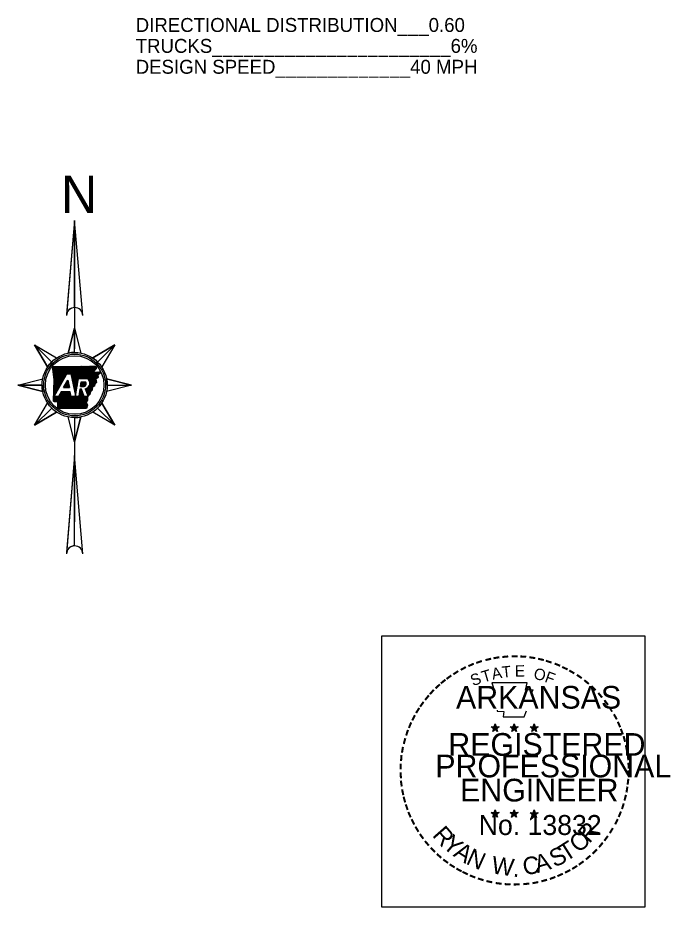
# Model space of a CAD drawing. Extents: x 541267 to 698737, y 790528 to 880942.
# Drawn here: x 633670 to 661200, y 793053 to 830549 of the extents above; entities that cross this region are included whole.
import ezdxf

# ---------------------------------------------------------------- set-up
doc = ezdxf.new("R2010")
doc.units = 0
for name, color, linetype in [('R_Border PE_RWC', 7, 'Continuous'), ('R_Draft', 7, 'Continuous'), ('R_No Plot', 7, 'Continuous'), ('R_Water Annot', 7, 'Continuous')]:
    doc.layers.add(name, color=color, linetype=linetype)

msp = doc.modelspace()

# ---------------------------------------------------------------- linework, layer by layer
at = {"layer": 'R_Border PE_RWC'}
for p, q in [((653647, 800662), (653814, 800609)), ((653647, 800662), (653768, 800640)), ((653647, 800662), (653761, 800603)), ((653711, 800467), (653814, 800609)), ((653711, 800467), (653771, 800583)), ((653711, 800467), (653813, 800570)), ((653814, 800783), (653795, 800663)), ((653916, 800467), (653813, 800569)), ((653814, 800609), (653814, 800783)), ((653814, 800783), (653838, 800664)), ((653980, 800662), (653814, 800609)), ((653916, 800467), (653814, 800609)), ((653980, 800662), (653843, 800638)), ((653916, 800467), (653851, 800606)), ((653980, 800662), (653883, 800613)), ((654446, 800662), (654613, 800609)), ((654446, 800662), (654567, 800640)), ((654446, 800662), (654560, 800603)), ((654510, 800467), (654613, 800609)), ((654510, 800467), (654570, 800583)), ((654510, 800467), (654612, 800570)), ((654613, 800783), (654594, 800663)), ((654715, 800467), (654612, 800569)), ((654613, 800609), (654613, 800783)), ((654613, 800783), (654637, 800664)), ((654779, 800662), (654613, 800609)), ((654715, 800467), (654613, 800609)), ((654779, 800662), (654642, 800638)), ((654715, 800467), (654650, 800606)), ((654779, 800662), (654682, 800613)), ((655290, 800656), (655457, 800603)), ((655290, 800656), (655411, 800635)), ((655290, 800656), (655404, 800598)), ((655354, 800461), (655457, 800603)), ((655354, 800461), (655414, 800578)), ((655354, 800461), (655456, 800565)), ((655457, 800778), (655438, 800657)), ((655559, 800461), (655456, 800563)), ((655457, 800603), (655457, 800778)), ((655457, 800778), (655481, 800658)), ((655623, 800656), (655457, 800603)), ((655559, 800461), (655457, 800603)), ((655623, 800656), (655486, 800633)), ((655559, 800461), (655493, 800600)), ((655623, 800656), (655526, 800607)), ((653812, 797160), (653793, 797040)), ((653812, 796985), (653812, 797160)), ((653812, 797160), (653836, 797040)), ((654611, 797160), (654591, 797040)), ((654611, 796985), (654611, 797160)), ((654611, 797160), (654634, 797040)), ((653645, 797039), (653812, 796985)), ((653645, 797039), (653766, 797017)), ((653645, 797039), (653759, 796980)), ((653709, 796843), (653812, 796985)), ((653709, 796843), (653769, 796960)), ((653709, 796843), (653811, 796947)), ((653914, 796843), (653811, 796946)), ((653978, 797039), (653812, 796985)), ((653914, 796843), (653812, 796985)), ((653978, 797039), (653841, 797015)), ((653914, 796843), (653849, 796983)), ((653978, 797039), (653881, 796990)), ((654444, 797039), (654611, 796985)), ((654444, 797039), (654565, 797017)), ((654444, 797039), (654557, 796980)), ((654507, 796843), (654611, 796985)), ((654507, 796843), (654568, 796960)), ((654507, 796843), (654610, 796947)), ((654713, 796843), (654610, 796946)), ((654777, 797039), (654611, 796985)), ((654713, 796843), (654611, 796985)), ((654777, 797039), (654640, 797015)), ((654713, 796843), (654647, 796983)), ((654777, 797039), (654679, 796990)), ((655289, 797034), (655456, 796981)), ((655289, 797034), (655410, 797012)), ((655289, 797034), (655403, 796975)), ((655353, 796839), (655456, 796981)), ((655353, 796839), (655413, 796955)), ((655353, 796839), (655455, 796942)), ((655456, 797155), (655437, 797035)), ((655558, 796839), (655455, 796941)), ((655456, 796981), (655456, 797155)), ((655456, 797155), (655480, 797036)), ((655622, 797034), (655456, 796981)), ((655558, 796839), (655456, 796981)), ((655622, 797034), (655485, 797010)), ((655558, 796839), (655493, 796978)), ((655622, 797034), (655525, 796985))]:
    msp.add_line(p, q, dxfattribs=at)
for points in [[(653667, 802517), (653795, 802122)], [(655347, 802076), (655415, 802212), (655087, 802201), (655158, 802517), (653667, 802517)], [(653902, 801358), (653902, 801316), (654172, 801307), (654146, 801081), (655040, 801081), (655137, 801337)], [(653814, 800783), (653916, 800467), (653647, 800662), (653980, 800662), (653711, 800467), (653814, 800783)], [(654613, 800783), (654715, 800467), (654446, 800662), (654779, 800662), (654510, 800467), (654613, 800783)], [(655457, 800778), (655559, 800461), (655290, 800656), (655623, 800656), (655354, 800461), (655457, 800778)], [(653812, 797160), (653914, 796843), (653645, 797039), (653978, 797039), (653709, 796843), (653812, 797160)], [(654611, 797160), (654713, 796843), (654444, 797039), (654777, 797039), (654507, 796843), (654611, 797160)], [(655456, 797155), (655558, 796839), (655289, 797034), (655622, 797034), (655353, 796839), (655456, 797155)]]:
    msp.add_lwpolyline(points, dxfattribs=at)
for centre, radius in [((653814, 800608), 82.4), ((653814, 800608), 69.2), ((653814, 800608), 55.4), ((653814, 800608), 47.4), ((653814, 800608), 35.8), ((653814, 800608), 23.7), ((653814, 800608), 14.2), ((654613, 800608), 82.4), ((654613, 800608), 69.2), ((654613, 800608), 55.4), ((654613, 800608), 47.4), ((654613, 800608), 35.8), ((654613, 800608), 23.7), ((654613, 800608), 14.2), ((655457, 800603), 82.4), ((655457, 800603), 69.2), ((655457, 800603), 55.4), ((655457, 800603), 47.4), ((655457, 800603), 35.8), ((655457, 800603), 23.7), ((655457, 800603), 14.2), ((653812, 796985), 82.4), ((653812, 796985), 69.2), ((653812, 796985), 55.4), ((653812, 796985), 47.4), ((653812, 796985), 35.8), ((653812, 796985), 23.7), ((653812, 796985), 14.2), ((654610, 796985), 82.4), ((654610, 796985), 69.2), ((654610, 796985), 55.4), ((654610, 796985), 47.4), ((654610, 796985), 35.8), ((654610, 796985), 23.7), ((654610, 796985), 14.2), ((655456, 796980), 82.4), ((655456, 796980), 69.2), ((655456, 796980), 55.4), ((655456, 796980), 47.4), ((655456, 796980), 35.8), ((655456, 796980), 23.7), ((655456, 796980), 14.2)]:
    msp.add_circle(centre, radius, dxfattribs=at)
at = {"layer": 'R_Draft'}
for p, q in [((636070, 822004), (635732, 818050)), ((636070, 822004), (636070, 816589)), ((636070, 818335), (636070, 822004)), ((635739, 818126), (635770, 818158)), ((635737, 818105), (635752, 818121)), ((636070, 817468), (635803, 816413)), ((636070, 816439), (636070, 817468)), ((634373, 816765), (635100, 816037)), ((635100, 816037), (634373, 816765)), ((634373, 816765), (634930, 815830)), ((637767, 816765), (636833, 816208)), ((637040, 816037), (637767, 816765)), ((637040, 816037), (637767, 816765)), ((635204, 814587), (635745, 815543)), ((635745, 815543), (635906, 815543)), ((635602, 814962), (635779, 815275)), ((636232, 815343), (636608, 815343)), ((636349, 815208), (636526, 815208)), ((638470, 815067), (637415, 815335)), ((633670, 815067), (634698, 815067)), ((634698, 815067), (633670, 815067)), ((633670, 815067), (634725, 814800)), ((635503, 814787), (635389, 814587)), ((635883, 814787), (635503, 814787)), ((635602, 814962), (635846, 814962)), ((636359, 814891), (636294, 814891)), ((636314, 815004), (636475, 815004)), ((636471, 814587), (636359, 814891)), ((636518, 814907), (636637, 814587)), ((637442, 815067), (638470, 815067)), ((637442, 815067), (638470, 815067)), ((635389, 814587), (635204, 814587)), ((636241, 814587), (635926, 814587)), ((636637, 814587), (636471, 814587)), ((634373, 813370), (635100, 814098)), ((635100, 814098), (634373, 813370)), ((637040, 814098), (637767, 813370)), ((637040, 814098), (637767, 813370)), ((637767, 813370), (637210, 814305)), ((634373, 813370), (635308, 813927)), ((636070, 812667), (636337, 813722)), ((636070, 813696), (636070, 813696)), ((636070, 813696), (636070, 809305)), ((636070, 813696), (636070, 812667)), ((636070, 812094), (635732, 808001)), ((636070, 808287), (636070, 812094))]:
    msp.add_line(p, q, dxfattribs=at)
for points in [[(636413, 817992), (636070, 822004), (635727, 817992)], [(635803, 816413), (636070, 817468), (636337, 816413)], [(634930, 815830), (634373, 816765), (635308, 816208)], [(636833, 816208), (637767, 816765), (637210, 815830)], [(635134, 815853), (635669, 815852), (636139, 815853), (636693, 815862), (636949, 815868)], [(635172, 814404), (635202, 815302), (635134, 815853)], [(635906, 815543), (636105, 814612), (636232, 815343)], [(637118, 815622), (637164, 815574), (637048, 815479), (637061, 815383), (636962, 815318), (636996, 815170), (636919, 815101), (636913, 815025), (636820, 814991), (636805, 814849), (636739, 814777), (636706, 814669), (636609, 814581), (636617, 814424), (636551, 814350), (636611, 814215), (636569, 814081)], [(636870, 815609), (637121, 815622)], [(634725, 814800), (633670, 815067), (634725, 815335)], [(635779, 815275), (635846, 814962)], [(636314, 815004), (636349, 815208)], [(637415, 815335), (638470, 815067), (637415, 814800)], [(635926, 814587), (635883, 814787)], [(636294, 814891), (636241, 814587)], [(635308, 813927), (634373, 813370), (634930, 814305)], [(636569, 814081), (635356, 814083), (635355, 814351)], [(637210, 814305), (637767, 813370), (636833, 813927)], [(636337, 813722), (636070, 812667), (635803, 813722)], [(636413, 807944), (636070, 812094), (635727, 807944)]]:
    msp.add_lwpolyline(points, dxfattribs=at)
for radius in [1372, 1235]:
    msp.add_circle((636070, 815067), radius, dxfattribs=at)
for centre, radius, start, end in [((636070, 817992), 343, 0, 180), ((636070, 817992), 343, 90, 170.2296), ((636070, 815067), 1372, 90, 101.2291), ((636070, 815067), 1372, 135, 146.2291), ((636070, 815067), 1372, 45, 56.2291), ((636436, 815122), 124, 288.1268, 43.8902), ((636468, 815145), 243, 281.8626, 54.8705), ((636070, 815067), 1372, 0, 11.2291), ((636070, 815067), 1372, 180, 191.2291), ((636070, 815067), 1372, 225, 236.2291), ((636070, 815067), 1372, 315, 326.2291), ((636070, 815067), 1372, 270, 281.2291), ((636070, 807944), 343, 0, 180), ((636070, 807944), 343, 90, 170.5511)]:
    msp.add_arc(centre, radius, start, end, dxfattribs=at)
for points in [[(636949, 815868), (636951, 815853), (636956, 815846), (636956, 815832), (636962, 815826), (636972, 815820), (636980, 815810), (636982, 815799), (636980, 815787), (636979, 815775), (636978, 815763), (636976, 815753), (636968, 815745), (636960, 815739), (636953, 815732), (636948, 815725), (636940, 815717), (636931, 815708), (636924, 815701), (636917, 815692), (636914, 815682), (636906, 815674), (636900, 815668), (636892, 815659), (636888, 815650), (636881, 815639), (636879, 815630), (636874, 815622), (636874, 815620)], [(635355, 814351), (635357, 814351), (635350, 814355), (635342, 814359), (635332, 814360), (635320, 814361), (635310, 814362), (635299, 814369), (635288, 814362), (635275, 814357), (635268, 814363), (635258, 814359), (635252, 814361), (635240, 814353), (635229, 814356), (635221, 814353), (635211, 814354), (635209, 814365), (635200, 814367), (635191, 814371), (635186, 814383), (635182, 814392), (635172, 814404)]]:
    msp.add_spline(points, degree=3, dxfattribs=at)
at = {"layer": 'R_No Plot'}
msp.add_lwpolyline([(649028, 804490), (660129, 804490), (660129, 793053), (649028, 793053)], close=True, dxfattribs=at)
at = {"layer": 'R_Water Annot'}
for p, q in [((635135, 815841), (635147, 815853)), ((635139, 815806), (635186, 815853)), ((635144, 815772), (635225, 815853)), ((635148, 815737), (635263, 815853)), ((635152, 815703), (635302, 815853)), ((635157, 815668), (635341, 815853)), ((635161, 815634), (635380, 815852)), ((635165, 815599), (635419, 815852)), ((635169, 815565), (635457, 815852)), ((635174, 815530), (635496, 815852)), ((635178, 815496), (635535, 815852)), ((635182, 815461), (635574, 815852)), ((635187, 815427), (635612, 815852)), ((635191, 815392), (635651, 815852)), ((635192, 815005), (636040, 815853)), ((635194, 815045), (636001, 815853)), ((635195, 815086), (635962, 815853)), ((635195, 815358), (635690, 815852)), ((635196, 815126), (635923, 815853)), ((635198, 815166), (635884, 815853)), ((635199, 815206), (635846, 815853)), ((635200, 815246), (635807, 815853)), ((635200, 815323), (635729, 815852)), ((635202, 815286), (635768, 815853)), ((635768, 815543), (636079, 815853)), ((635807, 815543), (636118, 815853)), ((635846, 815543), (636157, 815854)), ((635885, 815543), (636196, 815854)), ((635909, 815528), (636236, 815855)), ((635916, 815496), (636275, 815855)), ((635923, 815464), (636314, 815856)), ((635929, 815432), (636354, 815857)), ((635936, 815400), (636393, 815857)), ((635943, 815368), (636433, 815858)), ((635950, 815336), (636472, 815858)), ((635957, 815304), (636512, 815859)), ((635964, 815272), (636551, 815860)), ((635970, 815240), (636590, 815860)), ((635977, 815208), (636630, 815861)), ((635984, 815177), (636669, 815862)), ((635991, 815145), (636709, 815862)), ((635998, 815113), (636748, 815863)), ((636267, 815343), (636788, 815864)), ((636306, 815343), (636828, 815865)), ((636345, 815343), (636868, 815866)), ((636384, 815343), (636907, 815867)), ((636423, 815343), (636947, 815868)), ((636461, 815343), (636956, 815838)), ((636500, 815343), (636974, 815818)), ((636539, 815343), (636979, 815784)), ((636578, 815343), (636891, 815656)), ((636613, 815340), (636883, 815610)), ((636634, 815322), (636924, 815612)), ((636653, 815302), (636965, 815614)), ((636670, 815280), (637006, 815616)), ((636684, 815256), (637047, 815618)), ((636696, 815229), (637088, 815621)), ((636705, 815199), (637125, 815619)), ((636710, 815166), (637143, 815598)), ((637125, 815542), (637161, 815577)), ((635187, 814845), (635562, 815220)), ((635188, 814885), (635613, 815310)), ((635190, 814925), (635664, 815399)), ((635191, 814965), (635714, 815489)), ((635604, 814962), (635803, 815161)), ((635650, 815047), (635796, 815193)), ((635701, 815137), (635789, 815225)), ((635751, 815226), (635783, 815257)), ((636005, 815081), (636225, 815301)), ((636011, 815049), (636217, 815254)), ((636018, 815017), (636208, 815207)), ((636025, 814985), (636200, 815160)), ((636314, 815004), (636518, 815208)), ((636322, 815051), (636479, 815208)), ((636330, 815098), (636441, 815208)), ((636338, 815145), (636402, 815208)), ((636346, 815192), (636363, 815208)), ((636353, 815004), (636540, 815191)), ((636392, 815004), (636553, 815165)), ((636542, 814842), (636972, 815272)), ((636553, 814814), (636980, 815241)), ((636563, 814786), (636987, 815209)), ((636574, 814757), (636994, 815178)), ((636669, 815007), (636965, 815304)), ((636702, 815080), (637055, 815432)), ((636710, 815127), (637050, 815466)), ((637011, 815350), (637059, 815398)), ((635182, 814684), (635360, 814863)), ((635183, 814724), (635411, 814952)), ((635184, 814765), (635461, 815042)), ((635186, 814805), (635512, 815131)), ((635187, 814380), (635595, 814787)), ((635210, 814364), (635634, 814787)), ((635238, 814353), (635673, 814787)), ((635284, 814360), (635711, 814787)), ((635324, 814361), (635750, 814787)), ((635354, 814353), (635789, 814787)), ((635355, 814315), (635828, 814787)), ((635356, 814276), (635867, 814787)), ((635433, 814665), (635556, 814787)), ((635484, 814754), (635517, 814787)), ((635643, 814962), (635810, 815129)), ((635681, 814962), (635817, 815098)), ((635720, 814962), (635824, 815066)), ((635759, 814962), (635830, 815034)), ((635798, 814962), (635837, 815002)), ((635837, 814962), (635844, 814970)), ((636032, 814953), (636192, 815113)), ((636039, 814921), (636184, 815066)), ((636046, 814889), (636176, 815019)), ((636053, 814857), (636167, 814972)), ((636059, 814825), (636159, 814925)), ((636066, 814793), (636151, 814878)), ((636073, 814761), (636143, 814831)), ((636080, 814729), (636135, 814784)), ((636256, 814672), (636390, 814807)), ((636264, 814719), (636380, 814835)), ((636272, 814766), (636369, 814863)), ((636281, 814813), (636358, 814891)), ((636289, 814860), (636319, 814891)), ((636430, 815004), (636560, 815134)), ((636469, 815004), (636557, 815092)), ((636521, 814899), (636533, 814911)), ((636532, 814871), (636606, 814944)), ((636584, 814729), (636817, 814962)), ((636595, 814701), (636812, 814919)), ((636605, 814672), (636808, 814875)), ((636861, 815006), (636916, 815061)), ((635173, 814404), (635356, 814587)), ((635174, 814444), (635317, 814587)), ((635175, 814484), (635278, 814587)), ((635176, 814524), (635239, 814587)), ((635178, 814564), (635208, 814594)), ((635179, 814604), (635259, 814684)), ((635180, 814644), (635309, 814773)), ((635356, 814238), (635887, 814769)), ((635356, 814199), (635894, 814737)), ((635356, 814160), (635901, 814705)), ((635356, 814122), (635908, 814673)), ((635357, 814083), (635914, 814641)), ((635395, 814083), (635921, 814609)), ((635434, 814083), (635938, 814587)), ((635473, 814083), (635976, 814587)), ((635511, 814083), (636015, 814587)), ((635550, 814083), (636054, 814587)), ((635589, 814083), (636093, 814587)), ((635628, 814083), (636132, 814587)), ((635666, 814083), (636170, 814587)), ((635705, 814083), (636209, 814587)), ((635744, 814083), (636411, 814750)), ((635783, 814083), (636422, 814722)), ((635821, 814083), (636432, 814693)), ((635860, 814083), (636443, 814665)), ((635899, 814082), (636453, 814637)), ((635938, 814082), (636464, 814608)), ((635976, 814082), (636481, 814587)), ((636015, 814082), (636520, 814587)), ((636054, 814082), (636558, 814587)), ((636087, 814697), (636127, 814737)), ((636092, 814082), (636597, 814587)), ((636094, 814665), (636118, 814690)), ((636100, 814633), (636110, 814643)), ((636131, 814082), (636610, 814561)), ((636170, 814082), (636612, 814524)), ((636209, 814082), (636614, 814487)), ((636247, 814082), (636615, 814450)), ((636248, 814625), (636401, 814778)), ((636615, 814644), (636734, 814763)), ((636626, 814616), (636718, 814708)), ((636286, 814082), (636552, 814347)), ((636325, 814082), (636564, 814321)), ((636364, 814082), (636576, 814294)), ((636402, 814082), (636588, 814267)), ((636441, 814082), (636600, 814240)), ((636480, 814082), (636610, 814211)), ((636519, 814081), (636592, 814155)), ((636557, 814081), (636575, 814099))]:
    msp.add_line(p, q, dxfattribs=at)
msp.add_circle((636070, 815067), 1303, dxfattribs=at)

# ---------------------------------------------------------------- texts
at = {"layer": 'R_Border PE_RWC'}
for s, height, rotation, p in [('-', 766, 13.6302, (653427, 803172)), ('-', 766, 10.2193, (653751, 803249)), ('-', 766, 5.8968, (654100, 803302)), ('-', 766, 0.1862, (654469, 803336)), ('-', 766, 357.743, (654815, 803330)), ('-', 766, 352.1617, (655171, 803303)), ('-', 766, 347.2049, (655515, 803249)), ('-', 766, 28.7918, (652462, 802776)), ('-', 766, 24.3072, (652764, 802928)), ('-', 766, 19.1761, (653068, 803056)), ('A', 478, 11.2132, (653712, 802642)), ('T', 478, 6.0228, (654118, 802721)), ('E', 478, 0.8323, (654647, 802774)), ('-', 766, 342.3362, (655819, 803175)), ('-', 766, 337.8551, (656170, 803068)), ('-', 766, 334.1211, (656472, 802938)), ('-', 766, 36.2317, (651899, 802410)), ('-', 766, 34.0636, (652176, 802599)), ('S', 478, 21.594, (652880, 802363)), ('T', 478, 16.4036, (653317, 802522)), ('O', 478, 350.4515, (655415, 802673)), ('F', 478, 340.0707, (655871, 802564)), ('-', 766, 329.6409, (656749, 802803)), ('-', 766, 325.8627, (657057, 802630)), ('-', 766, 42.9622, (651465, 802030)), ('-', 766, 38.9507, (651672, 802229)), ('-', 766, 320.5297, (657349, 802426)), ('-', 766, 48.4231, (651250, 801801)), ('-', 766, 315.5786, (657635, 802193)), ('-', 766, 309.8797, (657908, 801930)), ('-', 766, 54.2325, (650860, 801297)), ('-', 766, 50.6142, (651057, 801568)), ('-', 766, 306.6522, (658159, 801642)), ('-', 766, 58.0706, (650704, 801045)), ('-', 670, 303.6753, (658391, 801370)), ('-', 766, 62.8713, (650555, 800751)), ('-', 766, 299.6684, (658544, 801080)), ('-', 766, 72.3945, (650326, 800158)), ('-', 766, 67.7743, (650431, 800459)), ('-', 766, 294.6628, (658699, 800787)), ('-', 766, 290.5728, (658822, 800511)), ('-', 766, 75.461, (650232, 799816)), ('-', 766, 285.1233, (658934, 800233)), ('-', 766, 81.2013, (650168, 799475)), ('-', 766, 280.5493, (659030, 799878)), ('-', 766, 85.1863, (650132, 799144)), ('-', 766, 276.5962, (659107, 799511)), ('-', 766, 89.0622, (650120, 798809)), ('-', 766, 274.3301, (659136, 799165)), ('-', 766, 94.1959, (650137, 798462)), ('-', 766, 269.9407, (659152, 798863)), ('-', 766, 98.9479, (650171, 798143)), ('-', 766, 263.5172, (659143, 798544)), ('-', 766, 101.7149, (650236, 797792)), ('-', 766, 260.9953, (659109, 798231)), ('-', 766, 105.4578, (650313, 797507)), ('-', 766, 255.7626, (659056, 797907)), ('-', 766, 109.0874, (650416, 797206)), ('-', 766, 252.8681, (658970, 797562)), ('-', 766, 114.0643, (650538, 796920)), ('-', 766, 115.7289, (650684, 796625)), ('-', 766, 244.6197, (658738, 796940)), ('-', 766, 247.8887, (658863, 797240)), ('-', 766, 120.4471, (650854, 796344)), ('R', 737, 311.3389, (651131, 796071)), ('R', 737, 48.6611, (657788, 795714)), ('-', 766, 239.0712, (658549, 796580)), ('-', 766, 125.8934, (651047, 796076)), ('Y', 737, 319.4491, (651549, 795611)), ('O', 737, 40.5509, (657331, 795309)), ('-', 766, 233.8452, (658357, 796267)), ('-', 766, 130.7181, (651268, 795812)), ('A', 737, 327.5593, (652009, 795226)), ('T', 737, 32.4407, (656796, 794953)), ('-', 766, 231.2538, (658151, 795997)), ('-', 766, 134.2238, (651516, 795551)), ('-', 766, 138.9338, (651767, 795329)), ('N', 737, 335.6695, (652544, 794893)), ('A', 737, 16.2204, (655593, 794488)), ('S', 737, 24.3305, (656306, 794719)), ('-', 766, 225.7653, (657922, 795727)), ('-', 766, 144.6463, (652033, 795135)), ('W.', 736.8, 351.8898, (653629, 794484)), ('C', 737, 8.1102, (655027, 794401)), ('-', 766, 215.7363, (657410, 795257)), ('-', 766, 221.0851, (657672, 795483)), ('-', 766, 148.0898, (652301, 794957)), ('-', 766, 151.5704, (652578, 794802)), ('-', 766, 154.6002, (652828, 794684)), ('-', 766, 207.3568, (656887, 794907)), ('-', 766, 212.2491, (657154, 795072)), ('-', 766, 158.5612, (653127, 794562)), ('-', 766, 162.7983, (653455, 794460)), ('-', 766, 167.5555, (653797, 794382)), ('-', 766, 195.4743, (655969, 794508)), ('-', 766, 200.7184, (656292, 794623)), ('-', 766, 204.2516, (656589, 794754)), ('-', 766, 173.1155, (654167, 794329)), ('-', 766, 176.5183, (654525, 794304)), ('-', 766, 181.5918, (654881, 794313)), ('-', 766, 185.8167, (655268, 794349)), ('-', 766, 191.2858, (655620, 794412))]:
    msp.add_text(s, height=height, rotation=rotation, dxfattribs=at).set_placement(p)
for s, height, p in [('ARKANSAS', 956.9, (652161, 801423)), ('REGISTERED', 956.9, (651837, 799437)), ('PROFESSIONAL', 956.89, (651287, 798527)), ('ENGINEER', 956.9, (652334, 797510)), ('No. 13832', 840.6, (653119, 796098))]:
    msp.add_text(s, height=height, dxfattribs=at).set_placement(p)
at = {"layer": 'R_Draft'}
for s, height, p in [('DIRECTIONAL DISTRIBUTION___0.60', 587.86, (638645, 829952)), ('TRUCKS_______________________6%', 587.86, (638645, 829070)), ('DESIGN SPEED_____________40 MPH', 587.86, (638645, 828189)), ('N', 1583, (635492, 822315)), ('DWB 7-27-17', 26.67, (635986, 813810))]:
    msp.add_text(s, height=height, dxfattribs=at).set_placement(p)

doc.saveas('drawing.dxf')
